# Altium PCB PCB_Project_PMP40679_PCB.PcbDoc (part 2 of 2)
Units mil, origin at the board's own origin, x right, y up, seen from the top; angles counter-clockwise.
Board outline 5118.11 x 3543.31 mil, 2 copper layers (Top Layer, Bottom Layer), stack 64.8 mil thick; 113 components, 55 nets, 272 pads, 364 vias.
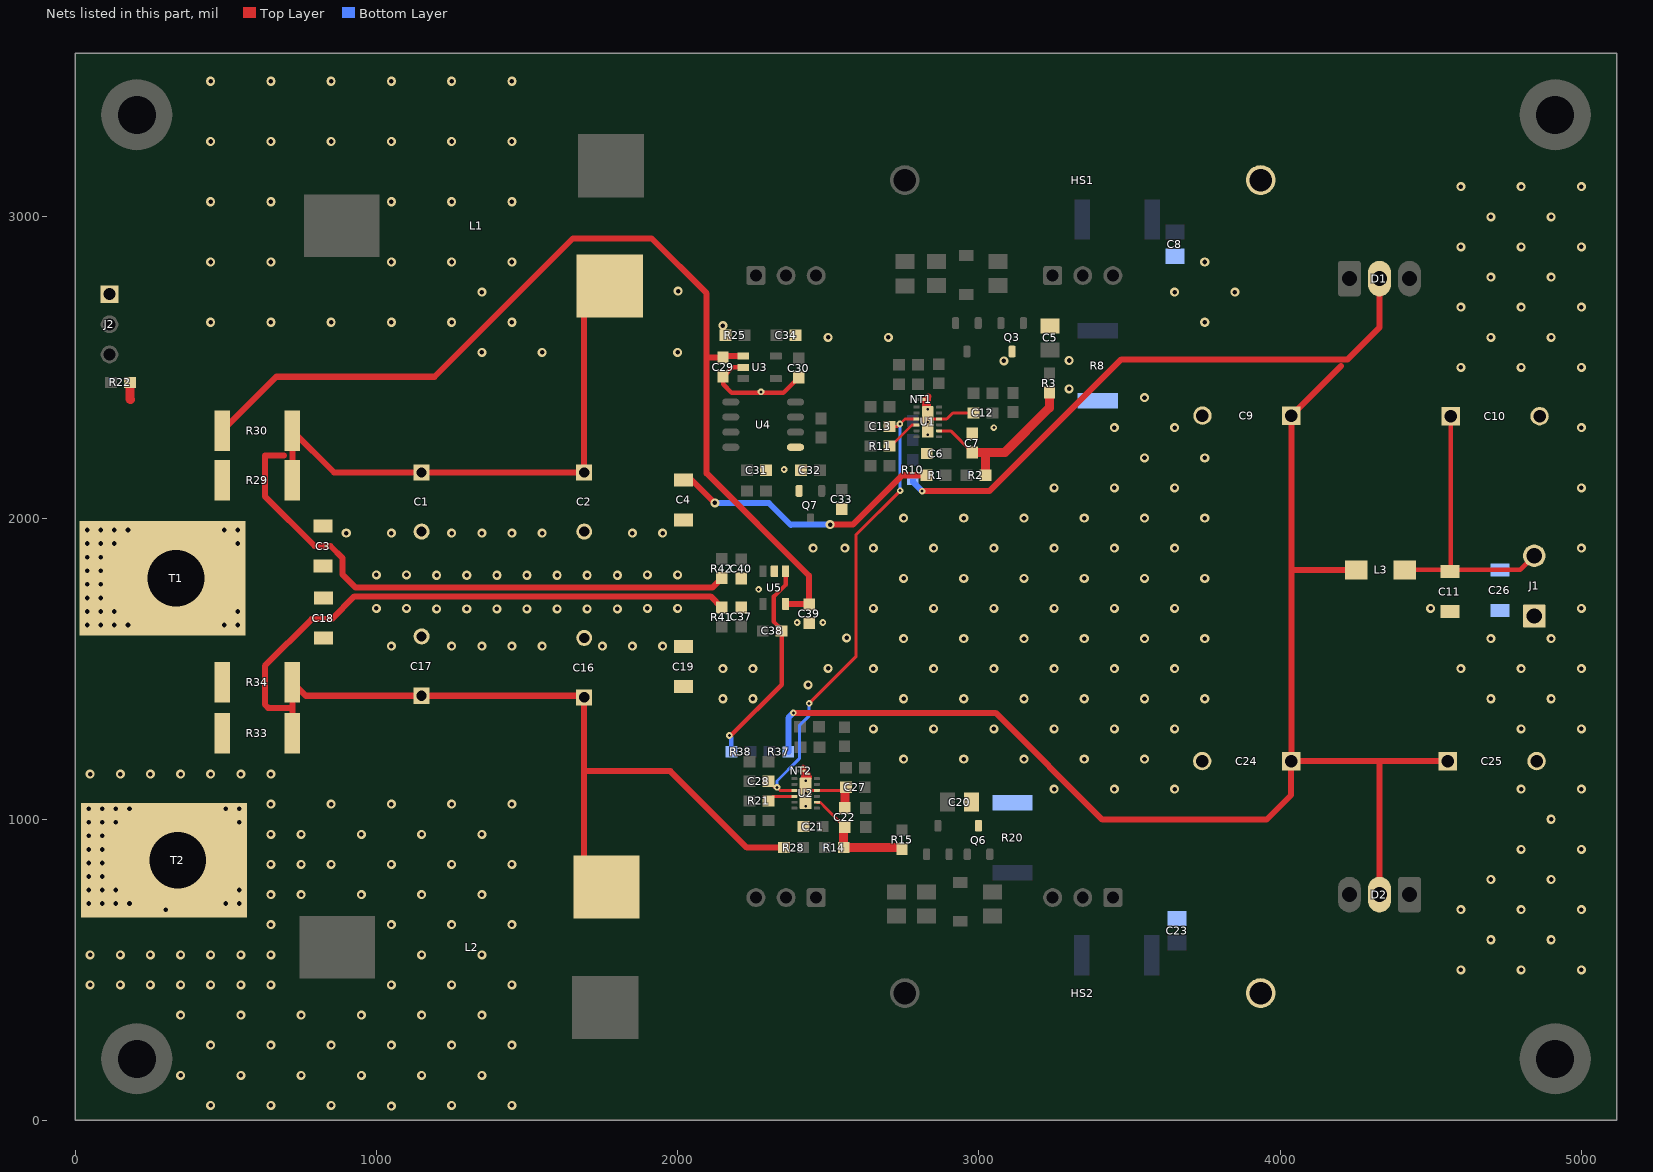
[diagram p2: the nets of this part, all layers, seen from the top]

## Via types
v1: diameter 30, hole 15, Top Layer to Bottom Layer, 279 vias
v2: diameter 32, hole 16, Top Layer to Bottom Layer, 56 vias
v3: diameter 22, hole 10, Top Layer to Bottom Layer, tented both sides, 23 vias
v4: diameter 19.68, hole 7.87, Top Layer to Bottom Layer, 6 vias

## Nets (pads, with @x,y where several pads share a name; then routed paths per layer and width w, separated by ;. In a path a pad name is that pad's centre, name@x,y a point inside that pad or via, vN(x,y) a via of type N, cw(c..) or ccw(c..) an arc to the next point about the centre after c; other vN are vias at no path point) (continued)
PGND: C1.2 C2.2 C3.2 C4.2 C5.2 C6.2 C7.2 C8.2 C9.2 C10.2 C11.2 C12.2 C16.2 C17.2 C18.2 C19.2 C20.2 C21.2 C22.2 C23.2 C24.2 C25.2 C26.2 C27.2 C29.2 C30.2 C31.2 C32.2 C33.2 C34.2 C37.2 C39.2 C40.2 HS1.2 HS2.1 J1.1 J2.1 NT1.1 NT2.1 Q3.3 Q6.3 Q7.2 R8.1 R20.1 R25.1 T2.1 U1.4 U1.13 U2.4 U2.13 U3.2 U4.1 U5.2 | length 1027.4
  Top Layer w10: 2416,1153.13 2416,1176.13 ; 2423.21,1154.15 2423.21,1173.15 ; U2.13@2434.84,1095.78 U2.4@2462.4,1095.78 2548.35,1095.78 C27.2@2555,1102.43 ; U1.13@2818.5,2361.32 2818.5,2331.01 v4(2830.51,2319) 2840.35,2328.84 U1.4@2867.91,2328.84 2893.35,2328.84 2913.5,2349 C12.2@2982.01,2349
  Top Layer w15: U3.2@2217.87,2500 2181.5,2500 C29.2@2151,2469.5 2151,2444 2179,2416 2351.5,2416 C30.2@2402,2466.5 ; NT1.1@2818.5,2394 2818.5,2373.33 v4(2830.51,2361.32)
  Top Layer w20: v4(2830.51,2361.32) 2831.5,2362.31 2831.5,2402 2832.5,2403
  Top Layer w30: 2428,1146.82 2425,1143.82 U2.13@2425,1133.82 ; 2430.4,1139.23 U2.13@2425,1133.82 ; C22.2@2555,1042.43 2555,1102.43 C27.2@2558.5,1105.94 ; U2.13@2425,1133.82 v4(2425,1085.94) v4(2425,1128.26) U2.13@2425,1133.82
  other v1: 1050,47.44 450,50 650,50 850,50 1250,50 1450,50 350,150 550,150 750,150 950,150 1150,150 1350,150 450,250 650,250 850,250 1050,250 1250,250 1450,250 350,350 550,350 750,350 950,350 1150,350 1350,350 50,450 150,450 250,450 350,450 450,450 550,450 650,450 1050,450 1250,450 1450,450 4600,500 4800,500 5000,500 50,550 150,550 250,550 350,550 450,550 550,550 650,550 1150,550 1350,550 4700,600 4900,600 650,650 1050,650 1250,650 1450,650 300,700 4600,700 4800,700 5000,700 650,750 750,750 950,750 1150,750 1350,750 4700,800 4900,800 650,850 750,850 850,850 1050,850 1250,850 1450,850 4800,900 5000,900 650,950 750,950 950,950 1150,950 1350,950 4900,1000 650,1050 850,1050 1050,1050 1250,1050 1450,1050 3250,1100 3450,1100 3650,1100 4800,1100 5000,1100 50,1150 150,1150 250,1150 350,1150 450,1150 550,1150 650,1150 2750,1200 2950,1200 3150,1200 3350,1200 3550,1200 2650,1300 2850,1300 3050,1300 3250,1300 3450,1300 3650,1300 4800,1300 5000,1300 2150,1400 2250,1400 2750,1400 2950,1400 3150,1400 3350,1400 3550,1400 3750,1400 4700,1400 4900,1400 2433,1446 2150,1500 2250,1500 2650,1500 2850,1500 3050,1500 3250,1500 3450,1500 3650,1500 4600,1500 4800,1500 5000,1500 2500,1501 1050,1575 1250,1575 1350,1575 1450,1575 1550,1575 1750,1575 1850,1575 1950,1575 2750,1600 2950,1600 3150,1600 3350,1600 3550,1600 3750,1600 4700,1600 4900,1600 2561,1602 1200,1698.43 1300,1698.43 1400,1698.43 1500,1698.43 1600,1698.43 1700,1698.43 1800,1698.43 1000,1700 1100,1700 1900,1700 2000,1700 2650,1700 2850,1700 3050,1700 3250,1700 3450,1700 3650,1700 4500,1700 5000,1700 2750,1800 2950,1800 3150,1800 3350,1800 3550,1800 3750,1800 1200,1810 1300,1810 1400,1810 1500,1810 1600,1810 1700,1810 1800,1810 1000,1811.57 1100,1811.57 1900,1811.57 2000,1811.57 2450,1900 2555,1900 2650,1900 2850,1900 3050,1900 3250,1900 3450,1900 3650,1900 5000,1900 900,1950 1050,1950 1250,1950 1350,1950 1450,1950 1550,1950 1850,1950 1950,1950 2750,2000 2950,2000 3150,2000 3350,2000 3550,2000 3750,2000 3250,2100 3450,2100 3650,2100 5000,2100 3550,2200 3750,2200 3450,2300 3650,2300 5000,2300 3550,2400 3300,2429 4600,2500 4800,2500 5000,2500 3083,2522 3300,2523 1350,2550 1550,2550 2000,2550 2500,2600 2700,2600 4700,2600 4900,2600 2150,2639 450,2650 650,2650 850,2650 1050,2650 1250,2650 1450,2650 3750,2650 4600,2700 4800,2700 5000,2700 1350,2750 3650,2750 3850,2750 2002,2753.43 4700,2800 4900,2800 450,2850 650,2850 1050,2850 1250,2850 1450,2850 3750,2850 4600,2900 4800,2900 5000,2900 4700,3000 4900,3000 450,3050 650,3050 1050,3050 1250,3050 1450,3050 4600,3100 4800,3100 5000,3100 450,3250 650,3250 850,3250 1050,3250 1250,3250 1450,3250 450,3450 650,3450 850,3450 1050,3450 1250,3450 1450,3450
  other v2: 45,720 90,720 135,720 180,720 500,720 545,720 45,765 90,765 135,765 545,765 45,810 90,810 45,855 90,855 45,900 90,900 45,945 90,945 45,990 90,990 135,990 545,990 45,1035 90,1035 135,1035 180,1035 500,1035 545,1035
  other v3: 2397,1653 2482,1653 2269,1763 2354,2161 3050,2300 2277,2419
  other v4: 2425,1043.61 2830.51,2276.68
RT1: R11.2 U1.10 | length 118.7
  Top Layer w10: R11.2@2703.5,2239 2708.5,2239 2778.5,2309 2792.95,2309 U1.10@2793.11,2309.16
RT2: R21.2 U2.10 | length 92.4
  Top Layer w10: R21.2@2301.5,1060.94 2316.65,1076.09 U2.10@2387.6,1076.09
SS: C13.1 C28.1 U1.9 U2.9 | length 1574.3
  Top Layer w10: C28.1@2301.5,1125.94 2321.43,1106 v3(2329.98,1106) 2340.2,1095.78 U2.9@2387.6,1095.78 ; v3(2437,1385) 2593,1541 2593,1945 v3(2739,2091) ; C13.1@2703.5,2304 2730,2304 v3(2738,2312) 2754.84,2328.84 U1.9@2793.11,2328.84
  Bottom Layer w10: v3(2329.98,1106) 2329.98,1126.98 2404,1201 2404,1311 2437,1344 v3(2437,1385) ; v3(2738,2312) 2738,2092 v3(2739,2091)
VC: C38.2 R38.2 U5.1 | length 691.5
  Top Layer w15: v3(2172,1278) 2177,1278 2346,1447 2346,1622.5 C38.2@2353.5,1630 ; C38.2@2344.5,1630.5 2320,1655 2320,1739.5 2358.4,1777.91 U5.1@2358.4,1809.13
  Bottom Layer w15: v3(2172,1278) 2178.5,1271.5 R38.2@2178.5,1224
VCC1: C7.1 R2.1 R3.2 U1.2 | length 587.9
  Top Layer w10: U1.2@2867.91,2289.47 2906.54,2289.47 C7.1@2978.5,2217.5
  Top Layer w20: R2.1@3022.01,2142 R2.1@3024,2143.99
  Top Layer w30: C7.1@2978.5,2217.5 3024,2217.5 ; R2.1@3022.01,2142 3022.01,2215.51 3024,2217.5 ; R3.2@3234.5,2416.5 3234.5,2365.5 3086.5,2217.5 3024,2217.5
VCC2: C22.1 R14.1 R15.2 U2.2 | length 392.4
  Top Layer w10: U2.2@2462.4,1056.41 2473.03,1056.41 2475.8,1053.65 2476.06,1053.65 2484.24,1045.46 2484.24,1045.2 C22.1@2555,974.44
  Top Layer w30: C22.1@2555,974.44 2551.5,970.94 R14.1@2551.5,905.94 2739.57,905.94 R15.2@2745,900.5
VIN: C3.1 C18.1 C29.1 C39.1 R22.2 R29.1 R30.1 R33.1 R34.1 T1.1 U3.1 U5.5 | length 3379.2
  Top Layer w20: R30.1@488.86,2290 667.86,2469 1193,2469 1652,2928 1914,2928 2096.3,2745.7 2096.3,2532 ; U3.1@2217.87,2537.4 2155.91,2537.4 C29.1@2151,2532.5 2096.8,2532.5 2096.3,2532 ; U5.5@2358.4,1714.87 C39.1@2435.63,1714.87 ; C39.1@2437,1713.5 C39.1@2435.63,1714.87 ; 2096.3,2532 2096.3,2148.7 2435.63,1809.37 C39.1@2435.63,1714.87
  Top Layer w30: R22.2@181.5,2450 181.5,2394.5 183,2393
  other v2: 40,1645 85,1645 130,1645 175,1645 495,1645 540,1645 40,1690 85,1690 130,1690 540,1690 40,1735 85,1735 40,1780 85,1780 40,1825 85,1825 40,1870 85,1870 40,1915 85,1915 130,1915 540,1915 40,1960 85,1960 130,1960 175,1960 495,1960 540,1960
VIN1: C1.1 C2.1 C4.1 L1.1 R1.2 R29.2 R30.2 R42.1 | length 4713.9
  Top Layer w20: 693,2207 630,2207 630,2072 795,1907 847.75,1907 887.87,1866.87 887.87,1812.13 931,1769 2115.5,1769 R42.1@2147,1800.5 ; R29.2@721.14,2077.86 R29.2@721.14,2125 R30.2@721.14,2290 859.29,2151.85 C1.1@1150,2151.85 C2.1@1690,2151.85 1690,2685.04 L1.1@1775.16,2770.2 ; C4.1@2020,2126.93 2046.07,2126.93 2123,2050 v1(2124,2050) ; v1(2506,1978) 2582,1978 2746,2142 R1.2@2826.02,2142
  Bottom Layer w20: v1(2124,2050) 2303,2050 2376,1977 2377,1978 v1(2506,1978)
VIN2: C16.1 C17.1 C19.1 L2.2 R28.2 R33.2 R34.2 R41.1 | length 4568.1
  Top Layer w20: R33.2@721.14,1285 721.14,1370 ; L2.2@1853.9,685 L2.2@1764.09,774.8 1690,848.9 1690,1160 ; R41.1@2147,1702.5 2109.5,1740 927,1740 851.37,1664.37 785.37,1664.37 630,1509 630,1381 641,1370 721.14,1370 ; R28.2@2353.5,905.94 2230.06,905.94 1976,1160 1690,1160 ; 721.14,1370 R34.2@721.14,1455 766.14,1410 C17.1@1150,1410 1685,1410 C16.1@1690,1405 1690,1160
VOUT: C10.1 C11.1 C26.1 J1.2 L3.2 | length 957.7
  Top Layer w15: L3.2@4414.71,1828 4797.35,1828 J1.2@4844,1874.65 ; C11.1@4564,1829.93 4566.36,1832.29 C10.1@4566.36,2338
VOUT1: C9.1 C24.1 C25.1 D1.2 D2.2 L3.1 R10.2 R37.2 | length 6602.3
  Top Layer w20: v3(2384,1353) 3056,1353 3410,999 3955,999 4036.64,1080.64 C24.1@4036.64,1193 C24.1@4037.64,1194 ; v3(2812,2089) 3035,2089 3473,2527 4224.64,2527 4330,2632.36 D1.2@4330,2798 ; 4201.64,2504 C9.1@4037.64,2340 4037.64,1830 ; L3.1@4253.29,1828 4039.64,1828 4037.64,1830 ; D2.2@4330,750 4330,1194 ; C25.1@4556.36,1193 4555.36,1194 4330,1194 ; C24.1@4037.64,1194 4330,1194 ; C24.1@4037.64,1194 4037.64,1830
  Bottom Layer w20: R37.2@2367.5,1224 2367.5,1336.5 v3(2384,1353) ; R10.2@2781,2129.5 2781,2120 v3(2812,2089)
pads on no net: HS1.1 HS2.2 L1.3 L2.3 U1.11 U2.11 U3.4 U4.5 U4.7

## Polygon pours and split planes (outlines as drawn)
PGND on Top Layer "TOP_LAYER_PGND_P084" (solid, remove dead copper, pour order 84): 5058,3535 5111,3482 5111,62 5059,10 62,10 7,65 7,3487 55,3535
AGND2 on Top Layer "TOP_LAYER_AGND2_P048" (solid, remove dead copper, pour order 48): 2397,1187 2428,1218 2428,1325 2424,1329 2334,1329 2214,1209 2214,1046 2222,1038 2258,1038 2263,1043 2263,1209 2281,1227 2334,1227 2357,1204 2357,1145 2372,1130 2396,1130 2397,1131
AGND1 on Top Layer "TOP_LAYER_AGND1_P046" (solid, remove dead copper, pour order 46): 2803,2366 2803,2404 2791,2416 2768,2416 2761,2423 2761,2529 2757,2533 2652,2533 2608,2489 2608,2232 2622,2218 2661,2218 2664,2221 2664,2387 2695,2418 2724,2418 2778,2364 2801,2364
VIN on Top Layer "TOP_LAYER_VIN_P044" (solid, remove dead copper, pour order 44): 733.5,1928.5 781,1881 841,1881 864,1858 864,1712 841,1689 769,1689 606,1526 606,1219 579.53,1192.53 191.74,1191.26 14,1369 14,2256 192,2434 582,2434 606,2410 606,2056
VIN1 on Top Layer "TOP_LAYER_VIN1_P042" (solid, remove dead copper, pour order 42): 650,2387 702,2439 1568,2439 1622,2493 1622,2860 1662,2900 1905,2900 1947,2858 1947,2493 2064,2376 2064,2097 2038,2071 868,2071 840,2043 700,2043 650,2093
VIN2 on Top Layer "TOP_LAYER_VIN2_P040" (solid, remove dead copper, pour order 40): 692,1530 840,1530 868,1502 2028,1502 2088,1442 2088,1215 1926,1053 1926,661 1896,631 1657,631 1619,669 1619,1051 1526,1144 719,1144 650,1213 650,1488
VOUT on Top Layer "TOP_LAYER_VOUT_P038" (solid, remove dead copper, pour order 38): 4462,2431 4702,2431 4732,2401 4732,2353 4732,2110 4794,2048 4876,2048 4953,1971 4953,1806 4891,1744 4379,1744 4329,1794 4329,1915 4413,1999 4413,2382
VOUT1 on Top Layer "TOP_LAYER_VOUT1_P036" (solid, remove dead copper, pour order 36): 4298,2854 4364,2854 4374,2844 4374,2717 4403,2688 4403,2005 4318,1920 4318,1656 4578,1396 4669,1305 4669,957 4569,857 4391,857 4372,838 4372,707 4351,686 4308,686 4288,706 4288,836 4267,857 4043,857 3911,989 3911,2531 4061,2681 4255.8,2681 4288,2713.2 4288,2844
NetD3_2 on Top Layer "TOP_LAYER_NETD3_2_P034" (solid, remove dead copper, pour order 34): 2718,2889 3111,2889 3115,2885 3115,2832 3109,2826 2718,2826 2710,2834 2710,2881
NetQ8_1 on Top Layer "TOP_LAYER_NETQ8_1_P032" (solid, remove dead copper, pour order 32): 3218.1,2843.1 3267.1,2843.1 3279.1,2831.1 3279.1,2775.1 3267.1,2763.1 3218.1,2763.1 3206.1,2775.1 3206.1,2831.1
NetQ2_3 on Top Layer "TOP_LAYER_NETQ2_3_P030" (solid, remove dead copper, pour order 30): 3423.1,2842.1 3472.1,2842.1 3484.1,2830.1 3484.1,2774.1 3472.1,2762.1 3423.1,2762.1 3411.1,2774.1 3411.1,2830.1
NetQ2_1 on Top Layer "TOP_LAYER_NETQ2_1_P028" (solid, remove dead copper, pour order 28): 2234,2843 2283,2843 2295,2831 2295,2775 2283,2763 2234,2763 2222,2775 2222,2831
NetQ2_3 on Top Layer "TOP_LAYER_NETQ2_3_P026" (solid, remove dead copper, pour order 26): 2438,2843 2487,2843 2499,2831 2499,2775 2487,2763 2438,2763 2426,2775 2426,2831
NetD1_1 on Top Layer "TOP_LAYER_NETD1_1_P024" (solid, remove dead copper, pour order 24): 3374,2750 3317,2750 3294,2773 3294,2871 3223,2942 3223,2952 3467,2952 3467,2942 3397,2872 3397,2773
NetD1_1 on Top Layer "TOP_LAYER_NETD1_1_P022" (solid, remove dead copper, pour order 22): 2388,2757 2331,2757 2308,2780 2308,2878 2237,2949 2237,2959 2481,2959 2481,2949 2411,2879 2411,2780
NetD1_1 on Top Layer "TOP_LAYER_NETD1_1_P020" (solid, remove dead copper, pour order 20): 1653,3465 4295,3465 4542,3218 4542,2787.56 4541.44,2787 4541.44,2743.44 4498,2700 4419,2700 4392,2727 4392,2858 4378,2872 4283,2872 4269,2858 4269,2724 4245,2700 4159,2700 4129,2730 4129,2832 4029,2932 2650,2932 2083,2932 2026,2989 1641,2989 1580,3050 1580,3392
NetD4_2 on Top Layer "TOP_LAYER_NETD4_2_P014" (solid, remove dead copper, pour order 14): 2687,707 3080,707 3084,703 3084,650 3078,644 2687,644 2679,652 2679,699
NetQ9_1 on Top Layer "TOP_LAYER_NETQ9_1_P012" (solid, remove dead copper, pour order 12): 3417,780 3472,780 3484,768 3484,712 3472,700 3423,700 3411,712 3411,774
NetQ5_3 on Top Layer "TOP_LAYER_NETQ5_3_P010" (solid, remove dead copper, pour order 10): 3217,780 3266,780 3278,768 3278,712 3266,700 3217,700 3205,712 3205,768
NetQ5_1 on Top Layer "TOP_LAYER_NETQ5_1_P008" (solid, remove dead copper, pour order 8): 2439,780 2488,780 2500,768 2500,712 2488,700 2439,700 2427,712 2427,768
NetQ5_3 on Top Layer "TOP_LAYER_NETQ5_3_P006" (solid, remove dead copper, pour order 6): 2231.1,780.1 2280.1,780.1 2292.1,768.1 2292.1,712.1 2280.1,700.1 2231.1,700.1 2219.1,712.1 2219.1,768.1
NetD2_1 on Top Layer "TOP_LAYER_NETD2_1_P004" (solid, remove dead copper, pour order 4): 3316,780 3373,780 3396,757 3396,659 3467,588 3467,578 3223,578 3223,588 3293,658 3293,757
NetD2_1 on Top Layer "TOP_LAYER_NETD2_1_P002" (solid, remove dead copper, pour order 2): 2330.5,792.5 2387.5,792.5 2410.5,769.5 2410.5,671.5 2481.5,600.5 2481.5,590.5 2237.5,590.5 2237.5,600.5 2307.5,670.5 2307.5,769.5
NetD2_1 on Top Layer "TOP_LAYER_NETD2_1_P000" (solid, remove dead copper, pour order 0): 1717,600 4092,600 4122,630 4122,800 4149,827 4248,827 4269,806 4269,690 4297,662 4365,662 4393,690 4393,808 4412,827 4498,827 4530,795 4530,356 4261,87 1631,87 1566,152 1566,449
NetQ2_3 on Bottom Layer "BOTTOM_LAYER_NETQ2_3_P064" (solid, remove dead copper, pour order 64): 2412,2880 2433,2901 3113,2901 3171,2843 3171,2776 3196,2751 3382,2751 3400,2769 3400,2835 3416,2851 3514,2851 3532,2833 3532,2568 3513,2549 2859,2549 2724,2684 2448,2684 2412,2720
NetD1_1 on Bottom Layer "BOTTOM_LAYER_NETD1_1_P062" (solid, remove dead copper, pour order 62): 3322,2844 3370,2844 3382,2832 3382,2776 3370,2764 3321,2764 3309,2776 3309,2831
NetQ8_1 on Bottom Layer "BOTTOM_LAYER_NETQ8_1_P060" (solid, remove dead copper, pour order 60): 3221.5,2844 3269.5,2844 3281.5,2832 3281.5,2776 3269.5,2764 3220.5,2764 3208.5,2776 3208.5,2831
NetQ2_1 on Bottom Layer "BOTTOM_LAYER_NETQ2_1_P058" (solid, remove dead copper, pour order 58): 2235,2844 2283,2844 2295,2832 2295,2776 2283,2764 2234,2764 2222,2776 2222,2831
NetD1_1 on Bottom Layer "BOTTOM_LAYER_NETD1_1_P056" (solid, remove dead copper, pour order 56): 2337,2844 2385,2844 2397,2832 2397,2776 2385,2764 2336,2764 2324,2776 2324,2831
NetD2_1 on Bottom Layer "BOTTOM_LAYER_NETD2_1_P054" (solid, remove dead copper, pour order 54): 3322,778 3370,778 3382,766 3382,710 3370,698 3321,698 3309,710 3309,765
NetD2_1 on Bottom Layer "BOTTOM_LAYER_NETD2_1_P052" (solid, remove dead copper, pour order 52): 2337,781 2385,781 2397,769 2397,713 2385,701 2336,701 2324,713 2324,768
NetQ5_3 on Bottom Layer "BOTTOM_LAYER_NETQ5_3_P050" (solid, remove dead copper, pour order 50): 2194,865 2217,888 3201,888 3285,804 3285,709 3203,627 2260,627 2194,693
NetQ5_1 on Bottom Layer "BOTTOM_LAYER_NETQ5_1_P018" (solid, remove dead copper, pour order 18): 2439,780 2487,780 2499,768 2499,712 2487,700 2438,700 2426,712 2426,767
NetQ9_1 on Bottom Layer "BOTTOM_LAYER_NETQ9_1_P016" (solid, remove dead copper, pour order 16): 3417,780 3472,780 3484,768 3484,712 3472,700 3423,700 3411,712 3411,774
NetD2_1 on Bottom Layer "BOTTOM_LAYER_NETD2_1_P066" (solid, remove dead copper, pour order 66): 3322,778 3370,778 3382,766 3382,657 3382,479 3374,471 3316,471 3309,478 3309,765
NetD1_1 on Bottom Layer "BOTTOM_LAYER_NETD1_1_P068" (solid, remove dead copper, pour order 68): 3368,2764 3320,2764 3308,2776 3308,2885 3308,3063 3316,3071 3374,3071 3381,3064 3381,2777
NetC8_1 on Bottom Layer "BOTTOM_LAYER_NETC8_1_P070" (solid, remove dead copper, pour order 70): 3541,3071 3591,3071 3689,2973 3689,2926 3683,2920 3541,2920 3533,2928 3533,3063
NetC23_1 on Bottom Layer "BOTTOM_LAYER_NETC23_1_P072" (solid, remove dead copper, pour order 72): 3542,625 3691,625 3697,619 3697,561 3606,470 3542,470 3534,478 3534,617
VOUT on Bottom Layer "BOTTOM_LAYER_VOUT_P080" (solid, remove dead copper, pour order 80): 4674,1953 4892,1953 4906,1939 4906,1803 4890,1787 4674,1787 4664,1797 4664,1943
PGND on Bottom Layer "BOTTOM_LAYER_PGND_P082" (solid, remove dead copper, pour order 82): 5058,3535 5111,3482 5111,62 5059,10 62,10 7,65 7,3487 55,3535

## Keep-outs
Keep-Out Layer:
  text ".Layer_Name" at 577,-858.49 h60

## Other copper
Top Layer:
  pour cut-out: 2196.93,967.93 2208,979 2219,968 2207.99,956.98
  pour cut-out: 2329,1887 2231,1887 2218,1900 2218,1998
  text ".Layer_Name" at 577,-858.49 h60
Bottom Layer:
  pour cut-out: 2329.39,794.39 2500.61,794.39 2516,779 2516,701 2505,690 2320,690 2308,702 2308,773 2329.39,794.39 2338,785 2497,785 2508,774 2508,705 2501,698 2327,698 2317,708 2317,765 2337.52,785.52
  text ".Layer_Name" at 577,-858.49 h60

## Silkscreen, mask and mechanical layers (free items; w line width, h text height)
Top Overlay:
  text "PMP40679" at 183,3073 h110
  text "Rev. E1" at 183,2968 h100
  text "GND" at 191,2721 h50
  text "EN" at 205,2623 h50
  text "EN_Pullup" at 194,2527 h50
  text "VIN" at 95,2025 h100
  text "VOUT" at 4356,1950 h100
  text "GND" at 4413,1567 h100
  text "GND" at 75,575 h100
  text ".Layer_Name" at 577,-858.49 h60
Bottom Overlay:
  text ".Layer_Name" at 577,-858.49 h60
Top Paste:
  text ".Layer_Name" at 577,-858.49 h60
Bottom Paste:
  text ".Layer_Name" at 577,-858.49 h60
Top Solder:
  rectangle: 1620,910 1926,958
  rectangle: 1620,999 1926,1047
  rectangle: 1624,2589 1947,2637
  rectangle: 1624,2495 1946,2543
  text ".Layer_Name" at 577,-858.49 h60
  text ".Layer_Name" at 577,-858.49 h60
Bottom Solder:
  text ".Layer_Name" at 577,-858.49 h60
Drill Guide:
  text ".Layer_Name" at 577,-858.49 h60
M1 Board Outline:
  the board outline again, w10
  text ".Layer_Name" at 577,-858.49 h60
M2 Board Dimensions:
  rectangle: 125,-400 500,-275
  rectangle: 0,-275 125,-150
  lines w7: 0,-275 1000,-275 ; 125,-400 125,-150 ; 250,-400 250,-150 ; 500,-400 500,-150 ; 750,-400 750,-150 ; 0,-400 0,-150 1000,-150 1000,-400 0,-400
  text ".Layer_Name" at 577,-858.49 h60
M3 3D STEP Top:
  text ".Layer_Name" at 577,-858.49 h60
M4 3D STEP Bottom:
  text ".Layer_Name" at 577,-858.49 h60
M5 Assembly Top:
  lines w10: -292,-930.17 6308,-930.17 ; -292,-726.83 6310,-726.83 ; -292,-523.5 -292,-1133.5 3713,-1133.5 6310,-1133.5 6310,-523.5 -291.5,-523.5 -291.5,-1133.5 1284,-1133.5 ; 2173,-1133.5 2173,-523.5 ; 3440,-726.83 3440,-523.5 ; 4280,-726.83 4280,-523.5 ; 4902,-1140 4902,-937.17
  text "COMPONENTS MARKED 'DNP' SHOULD NOT BE POPULATED." at 1153.5,-318.5 h60
  text "ASSEMBLY VARIANT:" at 1153,-434 h60
  text ".VariantName" at 2189,-434 h60
  text "PCB VIEWED FROM TOP SIDE" at -228.5,-655.67 h60
  text "BOARD #:" at 2248,-655.67 h60
  text ".PRJ_Number" at 2793.5,-655.67 h60
  text "REV:" at 3638,-655.67 h60
  text ".PCB_Rev" at 3929.5,-655.67 h60
  text "SVN REV:" at 4476,-655.67 h60
  text ".VersionControl_RevNumber" at 4982,-655.67 h60
  text "TID #:" at 2248,-859 h60
  text ".TID" at 2793.5,-859 h60
  text "PLOT NAME =" at -228.5,-1064.34 h60
  text ".plot_File_Name" at 577,-1064.34 h60
  text "GENERATED    :" at 2250,-1064.34 h60
  text ".Print_Date" at 3119.5,-1064.34 h60
  text ".Print_Time" at 3848.5,-1064.34 h60
  text "TEXAS INSTRUMENTS" at 5113,-1064.34 h60
M6 Assembly Bottom:
  lines w10: -292.5,-727.33 6309.5,-727.33 ; -290.5,-930.67 6309.5,-930.67 ; 1115.5,-1140.5 1115.5,-937.67 ; 1737.5,-727.33 1737.5,-524 ; 2577.5,-727.33 2577.5,-524 ; 3844.5,-1134 3844.5,-524 ; 4733.5,-1134 6309,-1134 6309,-524 -292.5,-524 -292.5,-1134 2304.5,-1134 6309.5,-1134 6309.5,-524
  text "COMPONENTS MARKED 'DNP' SHOULD NOT BE POPULATED." at 6102,-318 h60
  text ".VariantName" at 5058,-434 h60
  text "ASSEMBLY VARIANT:" at 6097,-434 h60
  text ".VersionControl_RevNumber" at 1035.5,-656.17 h60
  text "SVN REV:" at 1541.5,-656.17 h60
  text ".PCB_Rev" at 2088,-656.17 h60
  text "REV:" at 2379.5,-656.17 h60
  text ".PRJ_Number" at 3224,-656.17 h60
  text "BOARD #:" at 3769.5,-656.17 h60
  text "PCB VIEWED FROM BOTTOM SIDE" at 6246,-656.17 h60
  text ".TID" at 3224,-859.5 h60
  text "TID #:" at 3769.5,-859.5 h60
  text "TEXAS INSTRUMENTS" at 904.5,-1064.84 h60
  text ".Print_Time" at 2169,-1064.84 h60
  text ".Print_Date" at 2898,-1064.84 h60
  text "GENERATED    :" at 3767.5,-1064.84 h60
  text ".plot_File_Name" at 5440.5,-1064.84 h60
  text "PLOT NAME =" at 6246,-1064.84 h60
M9 Title Sheet:
  drawing of 57 lines, arcs and shapes, not listed
  text "1" at 739.84,8036.5 h70
  text "2" at 3235.5,8036.5 h70
  text "3" at 5724.84,8036.5 h70
  text "4" at 8231.51,8036.5 h70
  text "5" at 10730.5,8036.5 h70
  text "6" at 13235.5,8036.5 h70
  text "A" at -416.5,6893.5 h70
  text "A" at 14383.5,6893.5 h70
  text "B" at -416.5,4513.5 h70
  text "B" at 14383.5,4513.5 h70
  text "C" at -416.5,2138.5 h70
  text "C" at 14383.5,2138.5 h70
  text "PROJECT TITLE:" at 11343.5,277.5 h45
  text ".PRJ_Title" at 11393.5,144.17 h70
  text "DESIGNED FOR:" at 11343.5,-23.5 h45
  text ".PRJ_Customer" at 11393.5,-163.5 h70
  text "D" at -416.5,-231.5 h70
  text "D" at 14383.5,-231.5 h70
  text "FILE NAME:" at 11343.5,-323.5 h45
  text ".PCB_File_Name_No_Path" at 11393.5,-443.5 h70
  text "Texas Instruments (TI) and/or its licensors do not warrant the accuracy or completeness of this specification" at 6374,-605.34 h45
  text "ENGINEER:" at 11343.5,-613.5 h45
  text "LAYOUT BY:" at 12848.5,-613.5 h45
  text "or any information contained therein. TI and/or its licensors do not warrant that this design will meet" at 6329.01,-718 h45
  text ".PRJ_Engineer" at 11393.5,-768.49 h70
  text ".PCB_Layout" at 12899,-768.49 h70
  text "the specifications, will be suitable for your application or fit for any particular purpose, or will operate in" at 6329.01,-830.67 h45
  text ".Layer_Name" at 577,-858.49 h60
  text "ALTIUM DESIGNER VERSION:" at 12848.5,-923.5 h45
  text "an implementation. TI and/or its licensors do not warrant that the design is production worthy. You should" at 6329.01,-943.33 h45
  text "completely validate and test your design implementation to confirm the system functionality for your application." at 6374,-1056 h45
  text ".print_Scale" at 11393.5,-1056.83 h70
  text ".Application_BuildNumber" at 12899,-1056.83 h70
  text "1" at 739.84,-1263.5 h70
  text "2" at 3235.5,-1263.5 h70
  text "3" at 5724.84,-1263.5 h70
  text "4" at 8231.51,-1263.5 h70
  text "5" at 10730.5,-1263.5 h70
  text "6" at 13235.5,-1263.5 h70
M10 Fab Notes:
  drawing of 189 lines, arcs and shapes, not listed
  text "DESIGN INFORMATION" at 12382.02,6356.17 h60
  text "MIN. TRACK WIDTH:" at 11737.46,6224.05 h60
  text "8" at 12833.7,6224.05 h60
  text "MIL" at 12988.46,6224.05 h60
  text "MIN. CLEARANCE:" at 11737.46,6099.92 h60
  text "0.2" at 12773.7,6099.93 h60
  text "mm" at 12988.46,6099.92 h60
  text "MIN. VIA PAD SIZE:" at 11737.46,5975.8 h60
  text "24" at 12803.71,5975.8 h60
  text "MIL" at 12988.46,5975.8 h60
  text "0.05mm (2MIL)" at 12432.46,5845.9 h60
  text "MINIMUM ANNULAR RING" at 11408.23,5837.67 h60
  text "EXTERNAL" at 13140.46,5837.67 h60
  text "PER" at 11608.23,5727.55 h60
  text "IPC-D-275 CLASS 2 LEVEL C" at 11828.23,5727.54 h60
  text "MIL, HOLES" at 13316.46,5627.07 h60
  text "+/-" at 12924,5618.48 h60
  text "+/-" at 13778,5618.48 h60
  text "REGISTRATION TOLERANCES:" at 11408.23,5617.42 h60
  text "METAL" at 12608,5617.42 h60
  text "5" at 13184.2,5617.42 h60
  text "3" at 14017.2,5617.42 h60
  text "MIL" at 14133.46,5617.42 h60
  text "HOLE SIZE TOLERANCE (UNLESS OTHERWISE SPECIFIED):" at 11408.23,5519.1 h60
  text "+/-" at 13778,5516.23 h60
  text "3" at 14017.2,5515.17 h60
  text "MIL" at 14133.46,5515.17 h60
  text "MATERIAL:" at 11333.46,5377.52 h60
  text "FR-4 High Tg" at 12319.9,5249 h60
  text "X" at 12175.46,5241.01 h60
  text "FR-408" at 11754.46,5236.49 h60
  text "OTHER" at 13242.46,5236.49 h60
  text "62 MIL (1.6mm) +/-10%" at 12074.56,5093.46 h60
  text "X" at 11954.46,5091.01 h60
  text "THICKNESS:" at 11408.23,5085.24 h60
  text "OTHER" at 13359.46,5085.24 h60
  text "TOLERANCE:" at 11408.23,4946.92 h60
  text "X" at 12256.46,4946.92 h60
  text "ANSI IPC-6012 TYPE 3 CLASS 2" at 12434.48,4946.92 h60
  text "OTHER +/-" at 12434.46,4802.73 h60
  text "BOW & TWIST:" at 11408.23,4657.54 h60
  text "X" at 12256.46,4657.54 h60
  text "ANSI IPC-6012 TYPE 3 CLASS 2" at 12434.48,4657.54 h60
  text "OTHER +/-" at 12434.46,4510.85 h60
  text "DRILLING:" at 11333.46,4380.23 h60
  text "NC_DRILL FILES" at 13094.46,4275.04 h60
  text "REFERENCE:" at 11408.23,4271.1 h60
  text "X" at 12065.46,4271.01 h60
  text "AS SHOWN" at 12243.46,4271.1 h60
  text "X" at 12966.46,4271.1 h60
  text "OTHER" at 13392.46,4128.85 h60
  text "PTH COPPER THICKNESS:" at 11407.91,4125.32 h60
  text "X" at 12547.14,4125.32 h60
  text "20-30 um" at 12675.14,4125.32 h60
  text "BOARD FINISH:" at 11333.46,3977.73 h60
  text "SILKSCREEN:" at 11488.68,3867.6 h60
  text "X" at 12446.46,3867.6 h60
  text "TOP" at 12563.46,3867.6 h60
  text "X" at 12956.46,3867.6 h60
  text "BOTTOM" at 13074.46,3867.6 h60
  text "SILKSCREEN COLOR:" at 11488.68,3712.41 h60
  text "X" at 12445.46,3712.41 h60
  text "WHITE" at 12563.46,3712.41 h60
  text "OTHER" at 13074.46,3712.41 h60
  text "X" at 12576.46,3568.96 h60
  text "GREEN" at 12694.46,3568.96 h60
  text "OTHER" at 13312.46,3568.96 h60
  text "SOLDER RESIST COLOR:" at 11488.68,3562.1 h60
  text "X" at 12576.46,3414.71 h60
  text "MATTE" at 12694.46,3414.71 h60
  text "SEMI-GLOSS" at 13312,3414.07 h60
  text "IMMERSION GOLD (ENIG)" at 12394.46,3241.94 h60
  text "ENEPIG" at 13732,3234.72 h60
  text "SURFACE FINISH:" at 11333.46,3233.72 h60
  text "X" at 12216.46,3233.72 h60
  text "IMM. TIN/SILVER OR EQUIV" at 11663,3096.4 h60
  text "OTHER" at 13094.46,3092.47 h60
  text "ARRAY/PANEL:" at 11333.46,2937.09 h60
  text "CUT AND TRIM PER M1 BOARD OUTLINE" at 12394.46,2928.87 h60
  text "N.C. ROUTE" at 12394.46,2792.9 h60
  text "X" at 13082.46,2792.9 h60
  text "V. SCORE" at 13260.46,2792.9 h60
  text "CERTIFICATION:" at 11333.46,2663.77 h60
  text "MATERIALS AND WORKMANSHIP FOR ALL PCBS" at 12058.46,2663.77 h60
  text "TO MEET OR EXCEED THE REQUIREMENTS OF:" at 12058.46,2569.71 h60
  text "X" at 11695.97,2441.08 h60
  text "ANSI IPC-A-600F CLASS ->" at 11823.96,2441.08 h60
  text "X" at 13471.97,2441.08 h60
  text "2" at 13581.96,2441.08 h60
  text "1" at 13266.96,2439.58 h60
  text "3" at 13935.96,2439.58 h60
  text "X" at 12507.97,2293.39 h60
  text "RoHS" at 12635.96,2293.39 h60
  text "OTHER" at 13280.36,2293.39 h60
  text "PER ORDER" at 13677.42,2293.39 h60
  text "ALL BOARDS MUST MEET OR EXCEED UL94-V0 REQUIREMENTS." at 11361,2139.57 h60
  text "PCB MUST BEAR THE UL94V-0 UL REGISTERED MATERIAL ID NUMBER" at 11361,2023.5 h60
  text "ADDITIONAL REQUIREMENTS:" at 11333.46,1854.08 h60
  text "MICROSECTION:" at 11408.23,1746.95 h60
  text "YES" at 12313.96,1746.95 h60
  text "REQUIRED" at 13175.46,1602.62 h60
  text "BARE BOARD ELEC. TEST:" at 11408.23,1599.76 h60
  text "NONE" at 12713.96,1599.76 h60
  text "X" at 13057.46,1599.76 h60
  text "PER ORDER" at 13767.46,1599.76 h60
  text "XX MIL VIAS REQUIRE NON-CONDUCTIVE FILL AND PLANARIZE" at 11576.38,1394.82 h59
  text "XX MIL VIAS REQUIRE CONDUCTIVE FILL AND PLANARIZE" at 11584.38,1290.84 h60
  text "OUTER XX MIL TRACES REQUIRE 50 OHM SINGLE-ENDED IMPEDANCE" at 11583.39,1127.46 h58
  text "LAYER 2 & 3 (INNER LAYERS) XX MIL WIDE, XX MIL SPACE / TRACES REQUIRE 100 OHM DIFFERENTIAL IMPEDANCE" at 11575.39,891.74 h60
  text ".Layer_Name" at 577,-858.49 h60
M11 Gerber Information:
  lines w10: -292,-930.17 6308,-930.17 ; -292,-726.83 6310,-726.83 ; -292,-523.5 -292,-1133.5 3713,-1133.5 6310,-1133.5 6310,-523.5 -291.5,-523.5 -291.5,-1133.5 1284,-1133.5 ; 2173,-1133.5 2173,-523.5 ; 3440,-726.83 3440,-523.5 ; 4280,-726.83 4280,-523.5 ; 4902,-1140 4902,-937.17
  text "ALL ARTWORK VIEWED FROM TOP SIDE" at -228.5,-655.67 h60
  text "BOARD #:" at 2248,-655.67 h60
  text ".PRJ_Number" at 2793.5,-655.67 h60
  text "REV:" at 3638,-655.67 h60
  text ".PCB_Rev" at 3929.5,-655.67 h60
  text "SVN REV:" at 4476,-655.67 h60
  text ".VersionControl_RevNumber" at 4982,-655.67 h60
  text "LAYER NAME =" at -228.5,-858.49 h60
  text "TID #:" at 2248,-859 h60
  text ".TID" at 2793.5,-859 h60
  text "PLOT NAME =" at -228.5,-1064.34 h60
  text ".plot_File_Name" at 577,-1064.34 h60
  text "GENERATED    :" at 2250,-1064.34 h60
  text ".Print_Date" at 3119.5,-1064.34 h60
  text ".Print_Time" at 3848.5,-1064.34 h60
  text "TEXAS INSTRUMENTS" at 5113,-1064.34 h60
M12 Stackup:
  drawing of 191 lines, arcs and shapes, not listed
  text "Layer" at 9797.84,7830 h60
  text "Name" at 10207.76,7830 h60
  text "Material" at 11137.5,7830 h60
  text "Thickness" at 11997.27,7830 h60
  text "Constant" at 12647.1,7830 h60
  text "Board Layer Stack" at 13216.96,7830 h60
  text "1" at 9797.84,7710 h60
  text "Top Overlay" at 10207.76,7710 h60
  text "2" at 9797.84,7590 h60
  text "Top Solder" at 10207.76,7590 h60
  text "Solder Resist" at 11137.5,7590 h60
  text "0.40mil" at 11997.27,7590 h60
  text "3.5" at 12647.1,7590 h60
  text "3" at 9797.84,7470 h60
  text "Top Layer" at 10207.76,7470 h60
  text "Copper" at 11137.5,7470 h60
  text "2.80mil" at 11997.27,7470 h60
  text "4" at 9797.84,7350 h60
  text "Dielectric1" at 10207.76,7350 h60
  text "FR-4" at 11137.5,7350 h60
  text "59.20mil" at 11997.27,7350 h60
  text "4.8" at 12647.1,7350 h60
  text "5" at 9797.84,7230 h60
  text "Bottom Layer" at 10207.76,7230 h60
  text "Copper" at 11137.5,7230 h60
  text "2.80mil" at 11997.27,7230 h60
  text "6" at 9797.84,7110 h60
  text "Bottom Solder" at 10207.76,7110 h60
  text "Solder Resist" at 11137.5,7110 h60
  text "0.40mil" at 11997.27,7110 h60
  text "3.5" at 12647.1,7110 h60
  text "7" at 9797.84,6990 h60
  text "Bottom Overlay" at 10207.76,6990 h60
  text ".Layer_Name" at 577,-858.49 h60
M13 Component Bodies Top:
  text ".Layer_Name" at 577,-858.49 h60
M14 Component Bodies Bottom:
  text ".Layer_Name" at 577,-858.49 h60
M15 Courtyards Top:
  text ".Layer_Name" at 577,-858.49 h60
M16 Courtyards Bottom:
  text ".Layer_Name" at 577,-858.49 h60
Drill Drawing:
  circle w10: c5348.9,3003.91 r13.28
  circle w10: c5348.9,3003.91 r22.14
  circle w10: c5348.9,2206.93 r22.14
  lines w10: 5326.76,2129.45 5371.04,2129.45 5348.9,2085.17 5326.76,2129.45 ; 5326.76,2295.49 5337.83,2295.49 5337.83,2284.42 5359.97,2284.42 5359.97,2295.49 5371.04,2295.49 5371.04,2317.63 5359.97,2317.63 5359.97,2328.69 5337.83,2328.69 5337.83,2317.63 5326.76,2317.63 5326.76,2295.49 ; 5326.76,2384.04 5326.76,2395.11 5337.83,2406.18 5326.76,2417.25 5326.76,2428.32 5337.83,2428.32 5348.9,2417.25 5359.97,2428.32 5371.04,2428.32 5371.04,2417.25 5359.97,2406.18 5371.04,2395.11 5371.04,2384.04 5359.97,2384.04 5348.9,2395.11 5337.83,2384.04 5326.76,2384.04 ; 5326.76,2483.66 5371.04,2483.66 5371.04,2527.94 5326.76,2527.94 5326.76,2483.66 ; 5326.76,2594.35 5337.83,2594.35 5337.83,2583.29 5359.97,2583.29 5359.97,2594.35 5371.04,2594.35 5371.04,2616.49 5359.97,2616.49 5359.97,2627.56 5337.83,2627.56 5337.83,2616.49 5326.76,2616.49 5326.76,2594.35 ; 5326.76,2682.91 5371.04,2682.91 5371.04,2727.18 5326.76,2727.18 5326.76,2682.91 ; 5326.76,2782.53 5348.9,2793.6 5371.04,2782.53 5359.97,2804.67 5371.04,2826.81 5348.9,2815.74 5326.76,2826.81 5337.83,2804.67 5326.76,2782.53 ; 5326.76,2893.22 5337.83,2893.22 5348.9,2882.15 5359.97,2893.22 5371.04,2893.22 5359.97,2904.29 5371.04,2915.36 5359.97,2915.36 5348.9,2926.43 5337.83,2915.36 5326.76,2915.36 5337.83,2904.29 5326.76,2893.22 ; 5326.76,3081.4 5348.9,3092.47 5371.04,3081.4 5359.97,3103.54 5371.04,3125.67 5348.9,3114.6 5326.76,3125.67 5337.83,3103.54 5326.76,3081.4 ; 5326.76,3192.09 5337.83,3192.09 5348.9,3181.02 5359.97,3192.09 5371.04,3192.09 5359.97,3203.16 5371.04,3214.23 5359.97,3214.23 5348.9,3225.3 5337.83,3214.23 5326.76,3214.23 5337.83,3203.16 5326.76,3192.09 ; 5326.76,3324.92 5371.04,3324.92 5348.9,3280.64 5326.76,3324.92 ; 5335.62,2299.91 5342.26,2299.91 5342.26,2293.27 5355.54,2293.27 5355.54,2299.91 5362.18,2299.91 5362.18,2313.2 5355.54,2313.2 5355.54,2319.84 5342.26,2319.84 5342.26,2313.2 5335.62,2313.2 5335.62,2299.91 ; 5335.62,2691.76 5362.18,2691.76 5362.18,2718.33 5335.62,2718.33 5335.62,2691.76 ; 5335.62,3090.25 5348.9,3096.89 5362.18,3090.25 5355.54,3103.54 5362.18,3116.82 5348.9,3110.18 5335.62,3116.82 5342.26,3103.54 5335.62,3090.25 ; 5335.62,3196.52 5342.26,3196.52 5348.9,3189.87 5355.54,3196.52 5362.18,3196.52 5355.54,3203.16 5362.18,3209.8 5355.54,3209.8 5348.9,3216.44 5342.26,3209.8 5335.62,3209.8 5342.26,3203.16 5335.62,3196.52 ; 5335.62,3316.06 5362.18,3316.06 5348.9,3289.5 5335.62,3316.06
  lines w12: 5286,2055.29 8398.94,2055.29 ; 5286,3350.38 8398.94,3350.38 ; 5601.63,1955.66 5601.63,3450 ; 5918.82,1955.66 5918.82,3450 ; 6540.56,1955.66 6540.56,3450 ; 6784.88,1955.66 6784.88,3450 ; 7145.22,1955.66 7145.22,3450 ; 7854.73,1955.66 7854.73,3450 ; 5286,1955.66 8398.94,1955.66 8398.94,3450 5286,3450 5286,1955.66
  text "Symbol" at 5345.77,3380.26 h72
  text "Quantity" at 5631.52,3380.26 h72
  text "Finished Hole Size" at 5948.7,3380.26 h72
  text "Plated" at 6570.45,3380.26 h72
  text "Hole Type" at 6814.77,3380.26 h72
  text "Drill Layer Pair" at 7175.11,3380.26 h72
  text "Hole Tolerance" at 7884.62,3380.26 h72
  text "6" at 5631.52,3280.64 h60
  text "7.87mil (0.200mm)" at 5948.7,3280.64 h60
  text "PTH" at 6570.45,3280.64 h60
  text "Round" at 6814.77,3280.64 h60
  text "Top Layer - Bottom Layer" at 7175.11,3280.64 h60
  text "23" at 5631.52,3181.02 h60
  text "10.00mil (0.254mm)" at 5948.7,3181.02 h60
  text "PTH" at 6570.45,3181.02 h60
  text "Round" at 6814.77,3181.02 h60
  text "Top Layer - Bottom Layer" at 7175.11,3181.02 h60
  text "279" at 5631.52,3081.4 h60
  text "15.00mil (0.381mm)" at 5948.7,3081.4 h60
  text "PTH" at 6570.45,3081.4 h60
  text "Round" at 6814.77,3081.4 h60
  text "Top Layer - Bottom Layer" at 7175.11,3081.4 h60
  text "56" at 5631.52,2981.77 h60
  text "16.00mil (0.406mm)" at 5948.7,2981.77 h60
  text "PTH" at 6570.45,2981.77 h60
  text "Round" at 6814.77,2981.77 h60
  text "Top Layer - Bottom Layer" at 7175.11,2981.77 h60
  text "8" at 5631.52,2882.15 h60
  text "33.47mil (0.850mm)" at 5948.7,2882.15 h60
  text "PTH" at 6570.45,2882.15 h60
  text "Round" at 6814.77,2882.15 h60
  text "Top Layer - Bottom Layer" at 7175.11,2882.15 h60
  text "12" at 5631.52,2782.53 h60
  text "39.37mil (1.000mm)" at 5948.7,2782.53 h60
  text "PTH" at 6570.45,2782.53 h60
  text "Round" at 6814.77,2782.53 h60
  text "Top Layer - Bottom Layer" at 7175.11,2782.53 h60
  text "3" at 5631.52,2682.91 h60
  text "40.00mil (1.016mm)" at 5948.7,2682.91 h60
  text "PTH" at 6570.45,2682.91 h60
  text "Round" at 6814.77,2682.91 h60
  text "Top Layer - Bottom Layer" at 7175.11,2682.91 h60
  text "8" at 5631.52,2583.29 h60
  text "41.34mil (1.050mm)" at 5948.7,2583.29 h60
  text "PTH" at 6570.45,2583.29 h60
  text "Round" at 6814.77,2583.29 h60
  text "Top Layer - Bottom Layer" at 7175.11,2583.29 h60
  text "6" at 5631.52,2483.66 h60
  text "50.00mil (1.270mm)" at 5948.7,2483.66 h60
  text "PTH" at 6570.45,2483.66 h60
  text "Round" at 6814.77,2483.66 h60
  text "Top Layer - Bottom Layer" at 7175.11,2483.66 h60
  text "2" at 5631.52,2384.04 h60
  text "51.18mil (1.300mm)" at 5948.7,2384.04 h60
  text "PTH" at 6570.45,2384.04 h60
  text "Round" at 6814.77,2384.04 h60
  text "Top Layer - Bottom Layer" at 7175.11,2384.04 h60
  text "4" at 5631.52,2284.42 h60
  text "74.80mil (1.900mm)" at 5948.7,2284.42 h60
  text "PTH" at 6570.45,2284.42 h60
  text "Round" at 6814.77,2284.42 h60
  text "Top Layer - Bottom Layer" at 7175.11,2284.42 h60
  text "4" at 5631.52,2184.8 h60
  text "125.98mil (3.200mm)" at 5948.7,2184.8 h60
  text "PTH" at 6570.45,2184.8 h60
  text "Round" at 6814.77,2184.8 h60
  text "Top Layer - Bottom Layer" at 7175.11,2184.8 h60
  text "2" at 5631.52,2085.17 h60
  text "188.00mil (4.775mm)" at 5948.7,2085.17 h60
  text "PTH" at 6570.45,2085.17 h60
  text "Round" at 6814.77,2085.17 h60
  text "Top Layer - Bottom Layer" at 7175.11,2085.17 h60
  text "413 Total" at 5631.52,1985.55 h60
  text ".Layer_Name" at 577,-858.49 h60
Mechanical 17:
  text ".Layer_Name" at 577,-858.49 h60
Mechanical 18:
  text ".Layer_Name" at 577,-858.49 h60
Mechanical 19:
  text ".Layer_Name" at 577,-858.49 h60

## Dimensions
0,0 to 5118.11,0 on M2 Board Dimensions
0,0 to 0,3543.31 on M2 Board Dimensions
0,-400 to 1000,-400 on M2 Board Dimensions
